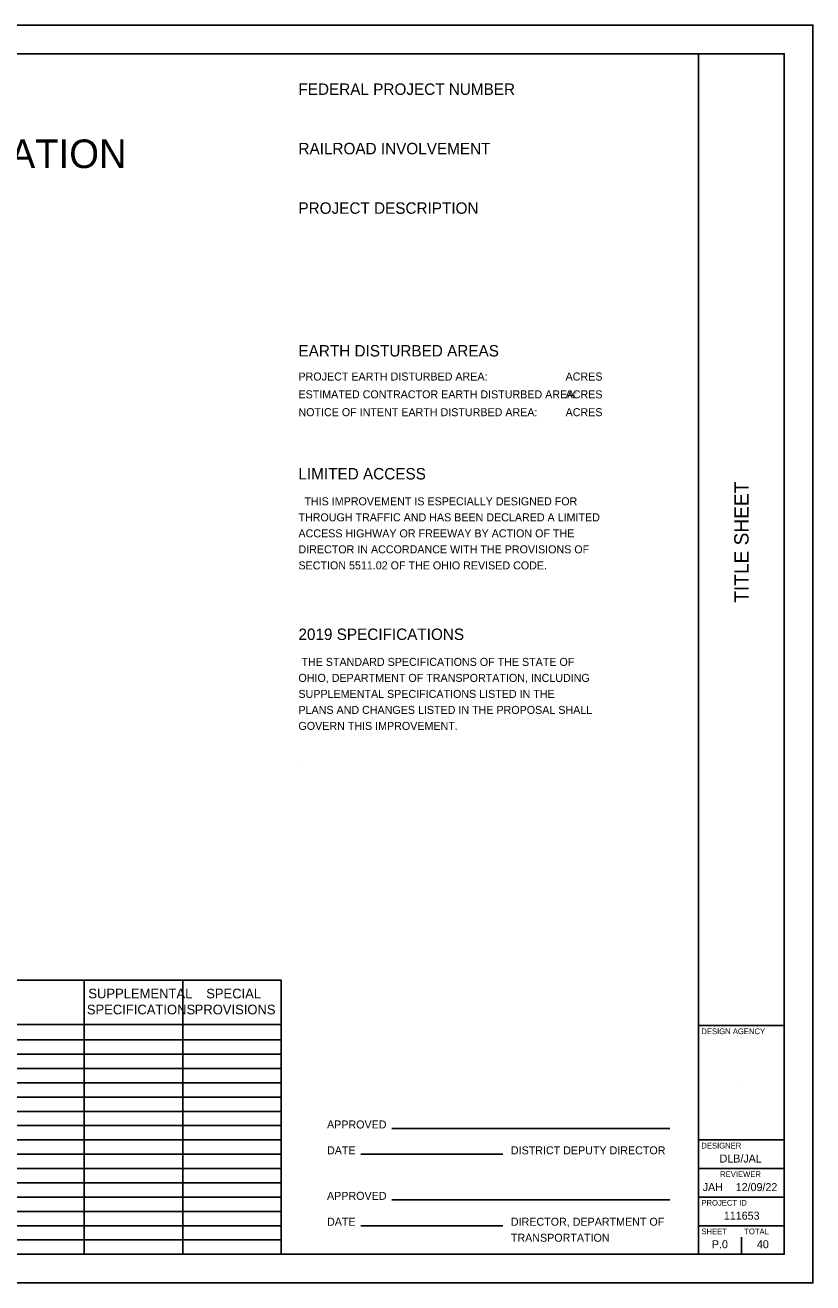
# Model space of a CAD drawing. Extents: x 0 to 34, y 0 to 22.
# Drawn here: x 20.22 to 34, y 0 to 22 of the extents above; entities that cross this region are included whole.
import ezdxf

# ---------------------------------------------------------------- set-up
doc = ezdxf.new("R2010")
doc.units = 0
for name, color, linetype in [('SH_Border', 7, 'Continuous'), ('SH_Cut_Line', 7, 'Continuous'), ('SH_Data', 7, 'Continuous'), ('SH_Text', 7, 'Continuous')]:
    doc.layers.add(name, color=color, linetype=linetype)

msp = doc.modelspace()

# ---------------------------------------------------------------- linework, layer by layer
at = {"layer": 'SH_Border'}
for p, q in [((32, 0.5), (32, 21.5)), ((32, 4.5), (33.5, 4.5)), ((32, 2.5), (33.5, 2.5)), ((32, 2), (33.5, 2)), ((32, 1.5), (33.5, 1.5)), ((32, 1), (33.5, 1))]:
    msp.add_line(p, q, dxfattribs=at)
msp.add_lwpolyline([(1.5, 21.5), (33.5, 21.5), (33.5, 0.5), (1.5, 0.5)], close=True, dxfattribs=at)
at = {"layer": 'SH_Cut_Line'}
msp.add_lwpolyline([(0, 0), (34, 0), (34, 22), (0, 22)], close=True, dxfattribs=at)
at = {"layer": 'SH_Data'}
for p, q in [((25, 9.06), (25, 9.06)), ((11.25, 5.292), (24.7, 5.292)), ((21.25, 0.5), (21.25, 5.292)), ((22.975, 0.5), (22.975, 5.292)), ((24.7, 0.5), (24.7, 5.292)), ((11.25, 4.521), (24.7, 4.521)), ((11.25, 4.25), (24.7, 4.25)), ((11.25, 4), (24.7, 4)), ((11.25, 3.75), (24.7, 3.75)), ((11.25, 3.5), (24.7, 3.5)), ((32.75, 3.5), (32.75, 3.5)), ((11.25, 3.25), (24.7, 3.25)), ((11.25, 3), (24.7, 3)), ((11.25, 2.75), (24.7, 2.75)), ((26.635, 2.7), (31.5, 2.7)), ((11.25, 2.5), (24.7, 2.5)), ((11.25, 2.25), (24.7, 2.25)), ((26.091, 2.248), (28.576, 2.248)), ((11.25, 2), (24.7, 2)), ((11.25, 1.75), (24.7, 1.75)), ((11.25, 1.5), (24.7, 1.5)), ((26.635, 1.452), (31.5, 1.452)), ((11.25, 1.25), (24.7, 1.25)), ((11.25, 1), (24.7, 1)), ((26.091, 0.999), (28.576, 0.999)), ((11.25, 0.75), (24.7, 0.75)), ((32.375, 0.675), (32.375, 0.675)), ((32.75, 0.5), (32.75, 0.8))]:
    msp.add_line(p, q, dxfattribs=at)

# ---------------------------------------------------------------- texts
msp.add_text('TITLE SHEET', height=0.25, rotation=90, dxfattribs=at).set_placement((32.875, 11.897))
for s, height, p in [('DESIGN AGENCY', 0.1, (32.05, 4.35)), ('DESIGNER', 0.1, (32.05, 2.35)), ('DLB/JAL', 0.14, (32.368, 2.105)), ('REVIEWER', 0.1, (32.378, 1.85)), ('JAH', 0.14, (32.073, 1.605)), ('12/09/22', 0.14, (32.65, 1.605)), ('PROJECT ID', 0.1, (32.05, 1.35)), ('111653', 0.14, (32.443, 1.105)), ('SHEET', 0.1, (32.05, 0.85)), ('TOTAL', 0.1, (32.8, 0.85)), ('P.0', 0.14, (32.233, 0.605)), ('40', 0.14, (33.021, 0.605))]:
    msp.add_text(s, height=height, dxfattribs=at).set_placement(p)
at = {"layer": 'SH_Text'}
for s, height, p in [('FEDERAL PROJECT NUMBER', 0.2, (25, 20.78)), ('DEPARTMENT OF TRANSPORTATION', 0.5, (9.92, 19.5)), ('RAILROAD INVOLVEMENT', 0.2, (25, 19.741)), ('PROJECT DESCRIPTION', 0.2, (25, 18.7)), ('EARTH DISTURBED AREAS', 0.2, (25, 16.204)), ('PROJECT EARTH DISTURBED AREA:', 0.14, (25, 15.784)), ('     ACRES', 0.14, (29.414, 15.784)), ('ESTIMATED CONTRACTOR EARTH DISTURBED AREA:', 0.14, (25, 15.472)), ('     ACRES', 0.14, (29.414, 15.472)), ('NOTICE OF INTENT EARTH DISTURBED AREA:', 0.14, (25, 15.16)), ('     ACRES', 0.14, (29.414, 15.16)), ('LIMITED ACCESS', 0.2, (25, 14.053)), ('  THIS IMPROVEMENT IS ESPECIALLY DESIGNED FOR', 0.14, (25, 13.601)), ('THROUGH TRAFFIC AND HAS BEEN DECLARED A LIMITED', 0.14, (25, 13.321)), ('ACCESS HIGHWAY OR FREEWAY BY ACTION OF THE', 0.14, (25, 13.04)), ('DIRECTOR IN ACCORDANCE WITH THE PROVISIONS OF', 0.14, (25, 12.761)), ('SECTION 5511.02 OF THE OHIO REVISED CODE.', 0.14, (25, 12.48)), ('2019 SPECIFICATIONS', 0.2, (25, 11.245)), (' THE STANDARD SPECIFICATIONS OF THE STATE OF', 0.14, (25, 10.792)), ('OHIO, DEPARTMENT OF TRANSPORTATION, INCLUDING', 0.14, (25, 10.512)), ('SUPPLEMENTAL SPECIFICATIONS LISTED IN THE', 0.14, (25, 10.232)), ('PLANS AND CHANGES LISTED IN THE PROPOSAL SHALL', 0.14, (25, 9.952)), ('GOVERN THIS IMPROVEMENT.', 0.14, (25, 9.672)), ('SUPPLEMENTAL', 0.17, (21.324, 4.976)), ('SPECIAL', 0.17, (23.386, 4.976)), ('SPECIFICATIONS', 0.17, (21.298, 4.696)), ('PROVISIONS', 0.17, (23.184, 4.696)), ('APPROVED', 0.14, (25.5, 2.7)), ('DATE', 0.14, (25.5, 2.248)), ('DISTRICT DEPUTY DIRECTOR', 0.14, (28.717, 2.248)), ('APPROVED', 0.14, (25.5, 1.452)), ('DATE', 0.14, (25.5, 0.999)), ('DIRECTOR, DEPARTMENT OF', 0.14, (28.717, 0.999)), ('TRANSPORTATION', 0.14, (28.717, 0.719))]:
    msp.add_text(s, height=height, dxfattribs=at).set_placement(p)

doc.saveas('drawing.dxf')
